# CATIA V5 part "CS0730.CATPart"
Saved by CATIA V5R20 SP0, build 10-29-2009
Part number: CS0730
Revision: 8
Definition: design
Nomenclature: CS0730
Source: made
Description: NOT SPECIFIED
Bounding box of the stored display mesh (mm): x -29 to 29, y -29 to 29, z -55 to 15
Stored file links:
  C:\Users\Raffaele\Desktop\3D X SITO CF\BOLEX\20-TILTED COLUMN SUPPORT\CS0730.CATPart
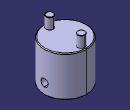
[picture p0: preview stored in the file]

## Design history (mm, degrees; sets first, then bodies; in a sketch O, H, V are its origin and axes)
Body1 "MANIFOLD_SOLID_BREP #715" (main body)
  Solid1: solid without history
